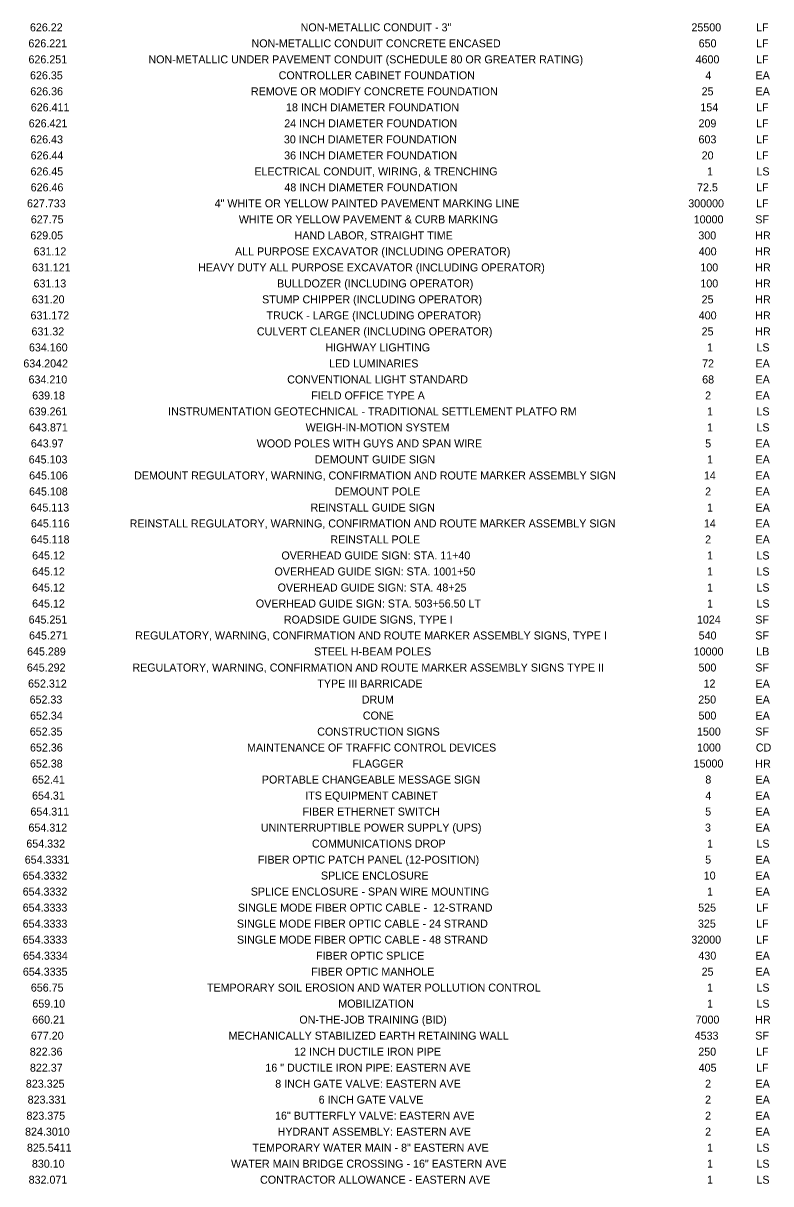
# Model space of a CAD drawing. Extents: x -18.7 to 5.6, y -2.7 to 5.1.
# Drawn here: x -18.677 to -17.757, y -1.71 to -0.282 of the extents above; entities that cross this region are included whole.
import ezdxf

# ---------------------------------------------------------------- set-up
doc = ezdxf.new("R2010")
doc.units = 0
doc.layers.add('ANNOTATION', color=7, linetype='Continuous')

msp = doc.modelspace()

# ---------------------------------------------------------------- texts
at = {"layer": 'ANNOTATION'}
for s, height, p in [('626.22', 0.00984, (-18.6685, -0.2925)), ('NON-METALLIC CONDUIT - 3"', 0.009843, (-18.3356, -0.2925)), ('25500', 0.00984, (-17.855, -0.2925)), ('LF', 0.00984, (-17.7755, -0.2925)), ('626.221', 0.00984, (-18.6704, -0.3122)), ('NON-METALLIC CONDUIT CONCRETE ENCASED', 0.009843, (-18.396, -0.3122)), ('650', 0.00984, (-17.8461, -0.3122)), ('LF', 0.00984, (-17.7755, -0.3122)), ('626.251', 0.00984, (-18.6703, -0.3319)), ('NON-METALLIC UNDER PAVEMENT CONDUIT (SCHEDULE 80 OR GREATER RATING)', 0.009843, (-18.5228, -0.3319)), ('4600', 0.00984, (-17.8499, -0.3319)), ('LF', 0.00984, (-17.7755, -0.3319)), ('626.35', 0.00984, (-18.6684, -0.3515)), ('CONTROLLER CABINET FOUNDATION', 0.009843, (-18.3626, -0.3515)), ('4', 0.00984, (-17.8378, -0.3515)), ('EA', 0.00984, (-17.7761, -0.3515)), ('626.36', 0.00984, (-18.6681, -0.3712)), ('REMOVE OR MODIFY CONCRETE FOUNDATION', 0.009843, (-18.3967, -0.3712)), ('25', 0.00984, (-17.8425, -0.3712)), ('EA', 0.00984, (-17.7761, -0.3712)), ('626.411', 0.00984, (-18.6675, -0.3909)), ('18 INCH DIAMETER FOUNDATION', 0.009843, (-18.3536, -0.3909)), ('154', 0.00984, (-17.844, -0.3909)), ('LF', 0.00984, (-17.7755, -0.3909)), ('626.421', 0.00984, (-18.67, -0.4106)), ('24 INCH DIAMETER FOUNDATION', 0.009843, (-18.3558, -0.4106)), ('209', 0.00984, (-17.8463, -0.4106)), ('LF', 0.00984, (-17.7755, -0.4106)), ('626.43', 0.00984, (-18.6681, -0.4303)), ('30 INCH DIAMETER FOUNDATION', 0.009843, (-18.3562, -0.4303)), ('603', 0.00984, (-17.8463, -0.4303)), ('LF', 0.00984, (-17.7755, -0.4303)), ('626.44', 0.00984, (-18.6676, -0.45)), ('36 INCH DIAMETER FOUNDATION', 0.009843, (-18.3559, -0.45)), ('20', 0.00984, (-17.8424, -0.45)), ('LF', 0.00984, (-17.7755, -0.45)), ('626.45', 0.00984, (-18.6678, -0.4697)), ('ELECTRICAL CONDUIT, WIRING, & TRENCHING', 0.009843, (-18.3925, -0.4697)), ('1', 0.00984, (-17.8358, -0.4697)), ('LS', 0.00984, (-17.7751, -0.4697)), ('626.46', 0.00984, (-18.6676, -0.4893)), ('48 INCH DIAMETER FOUNDATION', 0.009843, (-18.3556, -0.4893)), ('72.5', 0.00984, (-17.8481, -0.4893)), ('LF', 0.00984, (-17.7755, -0.4893)), ('627.733', 0.00984, (-18.6721, -0.509)), ('4" WHITE OR YELLOW PAINTED PAVEMENT MARKING LINE', 0.009843, (-18.4414, -0.509)), ('300000', 0.00984, (-17.8589, -0.509)), ('LF', 0.00984, (-17.7755, -0.509)), ('627.75', 0.00984, (-18.6674, -0.5287)), ('WHITE OR YELLOW PAVEMENT & CURB MARKING', 0.009843, (-18.4116, -0.5287)), ('10000', 0.00984, (-17.8522, -0.5287)), ('SF', 0.00984, (-17.7765, -0.5287)), ('629.05', 0.00984, (-18.668, -0.5484)), ('HAND LABOR, STRAIGHT TIME', 0.009843, (-18.343, -0.5484)), ('300', 0.00984, (-17.8465, -0.5484)), ('HR', 0.00984, (-17.7765, -0.5484)), ('631.12', 0.00984, (-18.664, -0.5681)), ('ALL PURPOSE EXCAVATOR (INCLUDING OPERATOR)', 0.009843, (-18.4163, -0.5681)), ('400', 0.00984, (-17.846, -0.5681)), ('HR', 0.00984, (-17.7765, -0.5681)), ('631.121', 0.00984, (-18.666, -0.5878)), ('HEAVY DUTY ALL PURPOSE EXCAVATOR (INCLUDING OPERATOR)', 0.009843, (-18.4617, -0.5878)), ('100', 0.00984, (-17.844, -0.5878)), ('HR', 0.00984, (-17.7765, -0.5878)), ('631.13', 0.00984, (-18.6641, -0.6075)), ('BULLDOZER (INCLUDING OPERATOR)', 0.009843, (-18.3646, -0.6075)), ('100', 0.00984, (-17.844, -0.6075)), ('HR', 0.00984, (-17.7765, -0.6075)), ('631.20', 0.00984, (-18.6662, -0.6271)), ('STUMP CHIPPER (INCLUDING OPERATOR)', 0.009843, (-18.383, -0.6271)), ('25', 0.00984, (-17.8425, -0.6271)), ('HR', 0.00984, (-17.7765, -0.6271)), ('631.172', 0.00984, (-18.6678, -0.6468)), ('TRUCK - LARGE (INCLUDING OPERATOR)', 0.009843, (-18.3776, -0.6468)), ('400', 0.00984, (-17.846, -0.6468)), ('HR', 0.00984, (-17.7765, -0.6468)), ('631.32', 0.00984, (-18.6666, -0.6665)), ('CULVERT CLEANER (INCLUDING OPERATOR)', 0.009843, (-18.3894, -0.6665)), ('25', 0.00984, (-17.8425, -0.6665)), ('HR', 0.00984, (-17.7765, -0.6665)), ('634.160', 0.00984, (-18.6697, -0.6862)), ('HIGHWAY LIGHTING', 0.009843, (-18.3051, -0.6862)), ('1', 0.00984, (-17.8358, -0.6862)), ('LS', 0.00984, (-17.7751, -0.6862)), ('634.2042', 0.00984, (-18.6766, -0.7059)), ('LED LUMINARIES', 0.009843, (-18.3005, -0.7059)), ('72', 0.00984, (-17.8419, -0.7059)), ('EA', 0.00984, (-17.7761, -0.7059)), ('634.210', 0.00984, (-18.6702, -0.7256)), ('CONVENTIONAL LIGHT STANDARD', 0.009843, (-18.3521, -0.7256)), ('68', 0.00984, (-17.8418, -0.7256)), ('EA', 0.00984, (-17.7761, -0.7256)), ('639.18', 0.00984, (-18.6657, -0.7453)), ('FIELD OFFICE TYPE A', 0.009843, (-18.3226, -0.7453)), ('2', 0.00984, (-17.8382, -0.7453)), ('EA', 0.00984, (-17.7761, -0.7453)), ('639.261', 0.00984, (-18.67, -0.7649)), ('INSTRUMENTATION GEOTECHNICAL - TRADITIONAL SETTLEMENT PLATFO RM', 0.009843, (-18.4985, -0.7649)), ('1', 0.00984, (-17.8358, -0.7649)), ('LS', 0.00984, (-17.7751, -0.7649)), ('643.871', 0.00984, (-18.6695, -0.7846)), ('WEIGH-IN-MOTION SYSTEM', 0.009843, (-18.3294, -0.7846)), ('1', 0.00984, (-17.8358, -0.7846)), ('LS', 0.00984, (-17.7751, -0.7846)), ('643.97', 0.00984, (-18.6674, -0.8043)), ('WOOD POLES WITH GUYS AND SPAN WIRE', 0.009843, (-18.3896, -0.8043)), ('5', 0.00984, (-17.8381, -0.8043)), ('EA', 0.00984, (-17.7761, -0.8043)), ('645.103', 0.00984, (-18.67, -0.824)), ('DEMOUNT GUIDE SIGN', 0.009843, (-18.318, -0.824)), ('1', 0.00984, (-17.8358, -0.824)), ('EA', 0.00984, (-17.7761, -0.824)), ('645.106', 0.00984, (-18.6695, -0.8437)), ('DEMOUNT REGULATORY, WARNING, CONFIRMATION AND ROUTE MARKER ASSEMBLY SIGN', 0.009843, (-18.5404, -0.8437)), ('14', 0.00984, (-17.8397, -0.8437)), ('EA', 0.00984, (-17.7761, -0.8437)), ('645.108', 0.00984, (-18.6696, -0.8634)), ('DEMOUNT POLE', 0.009843, (-18.2936, -0.8634)), ('2', 0.00984, (-17.8382, -0.8634)), ('EA', 0.00984, (-17.7761, -0.8634)), ('645.113', 0.00984, (-18.6678, -0.8831)), ('REINSTALL GUIDE SIGN', 0.009843, (-18.3234, -0.8831)), ('1', 0.00984, (-17.8358, -0.8831)), ('EA', 0.00984, (-17.7761, -0.8831)), ('645.116', 0.00984, (-18.6673, -0.9027)), ('REINSTALL REGULATORY, WARNING, CONFIRMATION AND ROUTE MARKER ASSEMBLY SIGN', 0.009843, (-18.5459, -0.9027)), ('14', 0.00984, (-17.8397, -0.9027)), ('EA', 0.00984, (-17.7761, -0.9027)), ('645.118', 0.00984, (-18.6674, -0.9224)), ('REINSTALL POLE', 0.009843, (-18.2991, -0.9224)), ('2', 0.00984, (-17.8382, -0.9224)), ('EA', 0.00984, (-17.7761, -0.9224)), ('645.12', 0.00984, (-18.6658, -0.9421)), ('OVERHEAD GUIDE SIGN: STA. 11+40', 0.009843, (-18.3592, -0.9421)), ('1', 0.00984, (-17.8358, -0.9421)), ('LS', 0.00984, (-17.7751, -0.9421)), ('645.12', 0.00984, (-18.6658, -0.9618)), ('OVERHEAD GUIDE SIGN: STA. 1001+50', 0.009843, (-18.3677, -0.9618)), ('1', 0.00984, (-17.8358, -0.9618)), ('LS', 0.00984, (-17.7751, -0.9618)), ('645.12', 0.00984, (-18.6658, -0.9815)), ('OVERHEAD GUIDE SIGN: STA. 48+25', 0.009843, (-18.3639, -0.9815)), ('1', 0.00984, (-17.8358, -0.9815)), ('LS', 0.00984, (-17.7751, -0.9815)), ('645.12', 0.00984, (-18.6658, -1.0012)), ('OVERHEAD GUIDE SIGN: STA. 503+56.50 LT', 0.009843, (-18.3907, -1.0012)), ('1', 0.00984, (-17.8358, -1.0012)), ('LS', 0.00984, (-17.7751, -1.0012)), ('645.251', 0.00984, (-18.6701, -1.0209)), ('ROADSIDE GUIDE SIGNS, TYPE I', 0.009843, (-18.3562, -1.0209)), ('1024', 0.00984, (-17.8482, -1.0209)), ('SF', 0.00984, (-17.7765, -1.0209)), ('645.271', 0.00984, (-18.6696, -1.0405)), ('REGULATORY, WARNING, CONFIRMATION AND ROUTE MARKER ASSEMBLY SIGNS, TYPE I', 0.009843, (-18.539, -1.0405)), ('540', 0.00984, (-17.8461, -1.0405)), ('SF', 0.00984, (-17.7765, -1.0405)), ('645.289', 0.00984, (-18.672, -1.0602)), ('STEEL H-BEAM POLES', 0.009843, (-18.3191, -1.0602)), ('10000', 0.00984, (-17.8522, -1.0602)), ('LB', 0.00984, (-17.7753, -1.0602)), ('645.292', 0.00984, (-18.6723, -1.0799)), ('REGULATORY, WARNING, CONFIRMATION AND ROUTE MARKER ASSEMBLY SIGNS TYPE II', 0.009843, (-18.5425, -1.0799)), ('500', 0.00984, (-17.8463, -1.0799)), ('SF', 0.00984, (-17.7765, -1.0799)), ('652.312', 0.00984, (-18.6708, -1.0996)), ('TYPE III BARRICADE', 0.009843, (-18.3151, -1.0996)), ('12', 0.00984, (-17.8401, -1.0996)), ('EA', 0.00984, (-17.7761, -1.0996)), ('652.33', 0.00984, (-18.6689, -1.1193)), ('DRUM', 0.00984, (-18.2604, -1.1193)), ('250', 0.00984, (-17.8466, -1.1193)), ('EA', 0.00984, (-17.7761, -1.1193)), ('652.34', 0.00984, (-18.6684, -1.139)), ('CONE', 0.00984, (-18.2591, -1.139)), ('500', 0.00984, (-17.8463, -1.139)), ('EA', 0.00984, (-17.7761, -1.139)), ('652.35', 0.00984, (-18.6687, -1.1587)), ('CONSTRUCTION SIGNS', 0.009843, (-18.3152, -1.1587)), ('1500', 0.00984, (-17.8482, -1.1587)), ('SF', 0.00984, (-17.7765, -1.1587)), ('652.36', 0.00984, (-18.6684, -1.1783)), ('MAINTENANCE OF TRAFFIC CONTROL DEVICES', 0.009843, (-18.4015, -1.1783)), ('1000', 0.00984, (-17.8481, -1.1783)), ('CD', 0.00984, (-17.7758, -1.1783)), ('652.38', 0.00984, (-18.6685, -1.198)), ('FLAGGER', 0.00984, (-18.272, -1.198)), ('15000', 0.00984, (-17.8523, -1.198)), ('HR', 0.00984, (-17.7765, -1.198)), ('652.41', 0.00984, (-18.6659, -1.2177)), ('PORTABLE CHANGEABLE MESSAGE SIGN', 0.009843, (-18.3833, -1.2177)), ('8', 0.00984, (-17.8379, -1.2177)), ('EA', 0.00984, (-17.7761, -1.2177)), ('654.31', 0.00984, (-18.6659, -1.2374)), ('ITS EQUIPMENT CABINET  ', 0.009843, (-18.3299, -1.2374)), ('4', 0.00984, (-17.8378, -1.2374)), ('EA', 0.00984, (-17.7761, -1.2374)), ('654.311', 0.00984, (-18.6679, -1.2571)), ('FIBER ETHERNET SWITCH ', 0.009843, (-18.3332, -1.2571)), ('5', 0.00984, (-17.8381, -1.2571)), ('EA', 0.00984, (-17.7761, -1.2571)), ('654.312', 0.00984, (-18.6703, -1.2768)), ('UNINTERRUPTIBLE POWER SUPPLY (UPS)', 0.009843, (-18.3845, -1.2768)), ('3', 0.00984, (-17.8383, -1.2768)), ('EA', 0.00984, (-17.7761, -1.2768)), ('654.332', 0.00984, (-18.6729, -1.2965)), ('COMMUNICATIONS DROP', 0.009843, (-18.3217, -1.2965)), ('1', 0.00984, (-17.8358, -1.2965)), ('LS', 0.00984, (-17.7751, -1.2965)), ('654.3331', 0.00984, (-18.6749, -1.3162)), ('FIBER OPTIC PATCH PANEL (12-POSITION)', 0.009843, (-18.3881, -1.3162)), ('5', 0.00984, (-17.8381, -1.3162)), ('EA', 0.00984, (-17.7761, -1.3162)), ('654.3332', 0.00984, (-18.6774, -1.3358)), ('SPLICE ENCLOSURE', 0.009843, (-18.3106, -1.3358)), ('10', 0.00984, (-17.8399, -1.3358)), ('EA', 0.00984, (-17.7761, -1.3358)), ('654.3332', 0.00984, (-18.6774, -1.3555)), ('SPLICE ENCLOSURE - SPAN WIRE MOUNTING', 0.009843, (-18.3969, -1.3555)), ('1', 0.00984, (-17.8358, -1.3555)), ('EA', 0.00984, (-17.7761, -1.3555)), ('654.3333', 0.00984, (-18.6774, -1.3752)), ('SINGLE MODE FIBER OPTIC CABLE -  12-STRAND', 0.009843, (-18.4127, -1.3752)), ('525', 0.00984, (-17.8467, -1.3752)), ('LF', 0.00984, (-17.7755, -1.3752)), ('654.3333', 0.00984, (-18.6774, -1.3949)), ('SINGLE MODE FIBER OPTIC CABLE - 24 STRAND', 0.009843, (-18.414, -1.3949)), ('325', 0.00984, (-17.847, -1.3949)), ('LF', 0.00984, (-17.7755, -1.3949)), ('654.3333', 0.00984, (-18.6774, -1.4146)), ('SINGLE MODE FIBER OPTIC CABLE - 48 STRAND', 0.009843, (-18.4139, -1.4146)), ('32000', 0.00984, (-17.8551, -1.4146)), ('LF', 0.00984, (-17.7755, -1.4146)), ('654.3334', 0.00984, (-18.6769, -1.4343)), ('FIBER OPTIC SPLICE ', 0.009843, (-18.3167, -1.4343)), ('430', 0.00984, (-17.8464, -1.4343)), ('EA', 0.00984, (-17.7761, -1.4343)), ('654.3335', 0.00984, (-18.6772, -1.454)), ('FIBER OPTIC MANHOLE ', 0.009843, (-18.3226, -1.454)), ('25', 0.00984, (-17.8425, -1.454)), ('EA', 0.00984, (-17.7761, -1.454)), ('656.75', 0.00984, (-18.6674, -1.4736)), ('TEMPORARY SOIL EROSION AND WATER POLLUTION CONTROL', 0.009843, (-18.4508, -1.4736)), ('1', 0.00984, (-17.8358, -1.4736)), ('LS', 0.00984, (-17.7751, -1.4736)), ('659.10', 0.00984, (-18.6655, -1.4933)), ('MOBILIZATION', 0.009843, (-18.2893, -1.4933)), ('1', 0.00984, (-17.8358, -1.4933)), ('LS', 0.00984, (-17.7751, -1.4933)), ('660.21', 0.00984, (-18.6657, -1.513)), ('ON-THE-JOB TRAINING (BID)', 0.009843, (-18.3372, -1.513)), ('7000', 0.00984, (-17.8499, -1.513)), ('HR', 0.00984, (-17.7765, -1.513)), ('677.20', 0.00984, (-18.6673, -1.5327)), ('MECHANICALLY STABILIZED EARTH RETAINING WALL', 0.009843, (-18.4243, -1.5327)), ('4533', 0.00984, (-17.851, -1.5327)), ('SF', 0.00984, (-17.7765, -1.5327)), ('822.36', 0.00984, (-18.6687, -1.5524)), ('12 INCH DUCTILE IRON PIPE', 0.009843, (-18.3436, -1.5524)), ('250', 0.00984, (-17.8466, -1.5524)), ('LF', 0.00984, (-17.7755, -1.5524)), ('822.37', 0.00984, (-18.6685, -1.5721)), ('16 " DUCTILE IRON PIPE: EASTERN AVE', 0.009843, (-18.379, -1.5721)), ('405', 0.00984, (-17.8461, -1.5721)), ('LF', 0.00984, (-17.7755, -1.5721)), ('823.325', 0.00984, (-18.6735, -1.5918)), ('8 INCH GATE VALVE: EASTERN AVE', 0.009843, (-18.3668, -1.5918)), ('2', 0.00984, (-17.8382, -1.5918)), ('EA', 0.00984, (-17.7761, -1.5918)), ('823.331', 0.00984, (-18.6713, -1.6114)), ('6 INCH GATE VALVE', 0.009843, (-18.3134, -1.6114)), ('2', 0.00984, (-17.8382, -1.6114)), ('EA', 0.00984, (-17.7761, -1.6114)), ('823.375', 0.00984, (-18.6728, -1.6311)), ('16" BUTTERFLY VALVE: EASTERN AVE', 0.009843, (-18.3671, -1.6311)), ('2', 0.00984, (-17.8382, -1.6311)), ('EA', 0.00984, (-17.7761, -1.6311)), ('824.3010', 0.00984, (-18.6745, -1.6508)), ('HYDRANT ASSEMBLY: EASTERN AVE', 0.009843, (-18.3639, -1.6508)), ('2', 0.00984, (-17.8382, -1.6508)), ('EA', 0.00984, (-17.7761, -1.6508)), ('825.5411', 0.00984, (-18.6722, -1.6705)), ('TEMPORARY WATER MAIN - 8" EASTERN AVE', 0.009843, (-18.3949, -1.6705)), ('1', 0.00984, (-17.8358, -1.6705)), ('LS', 0.00984, (-17.7751, -1.6705)), ('830.10', 0.00984, (-18.6661, -1.6902)), ('WATER MAIN BRIDGE CROSSING - 16" EASTERN AVE', 0.009843, (-18.4212, -1.6902)), ('1', 0.00984, (-17.8358, -1.6902)), ('LS', 0.00984, (-17.7751, -1.6902)), ('832.071', 0.00984, (-18.6701, -1.7099)), ('CONTRACTOR ALLOWANCE - EASTERN AVE', 0.009843, (-18.3855, -1.7099)), ('1', 0.00984, (-17.8358, -1.7099)), ('LS', 0.00984, (-17.7751, -1.7099))]:
    msp.add_text(s, height=height, dxfattribs=at).set_placement(p)

doc.saveas('drawing.dxf')
